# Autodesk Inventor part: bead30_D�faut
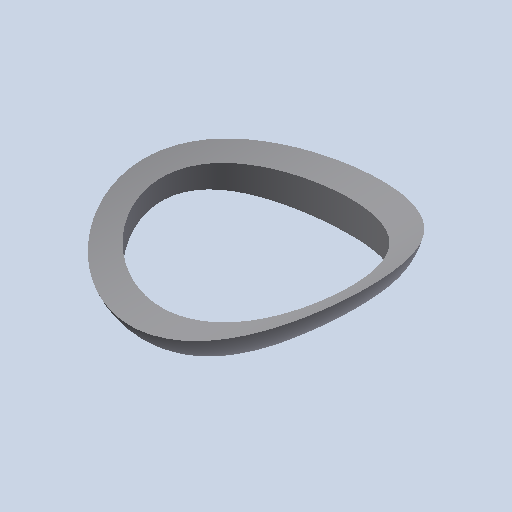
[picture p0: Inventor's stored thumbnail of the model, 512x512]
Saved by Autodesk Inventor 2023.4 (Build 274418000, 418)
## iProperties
Created: 2011-01
Part Number: bead30_D�faut
Document SubType Name: Modeling
Designer: eric
Density: 1 g/cm^3
Mass: 0.0717811 g
Surface Area: 2.42706 cm^2
Volume: 0.0717811 cm^3
Material: Générique
Appearance: Par défaut
Author: eric
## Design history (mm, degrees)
feature "Base1"
node "Corps solides"
node "Corps surfaciques"
node "Solide1"
